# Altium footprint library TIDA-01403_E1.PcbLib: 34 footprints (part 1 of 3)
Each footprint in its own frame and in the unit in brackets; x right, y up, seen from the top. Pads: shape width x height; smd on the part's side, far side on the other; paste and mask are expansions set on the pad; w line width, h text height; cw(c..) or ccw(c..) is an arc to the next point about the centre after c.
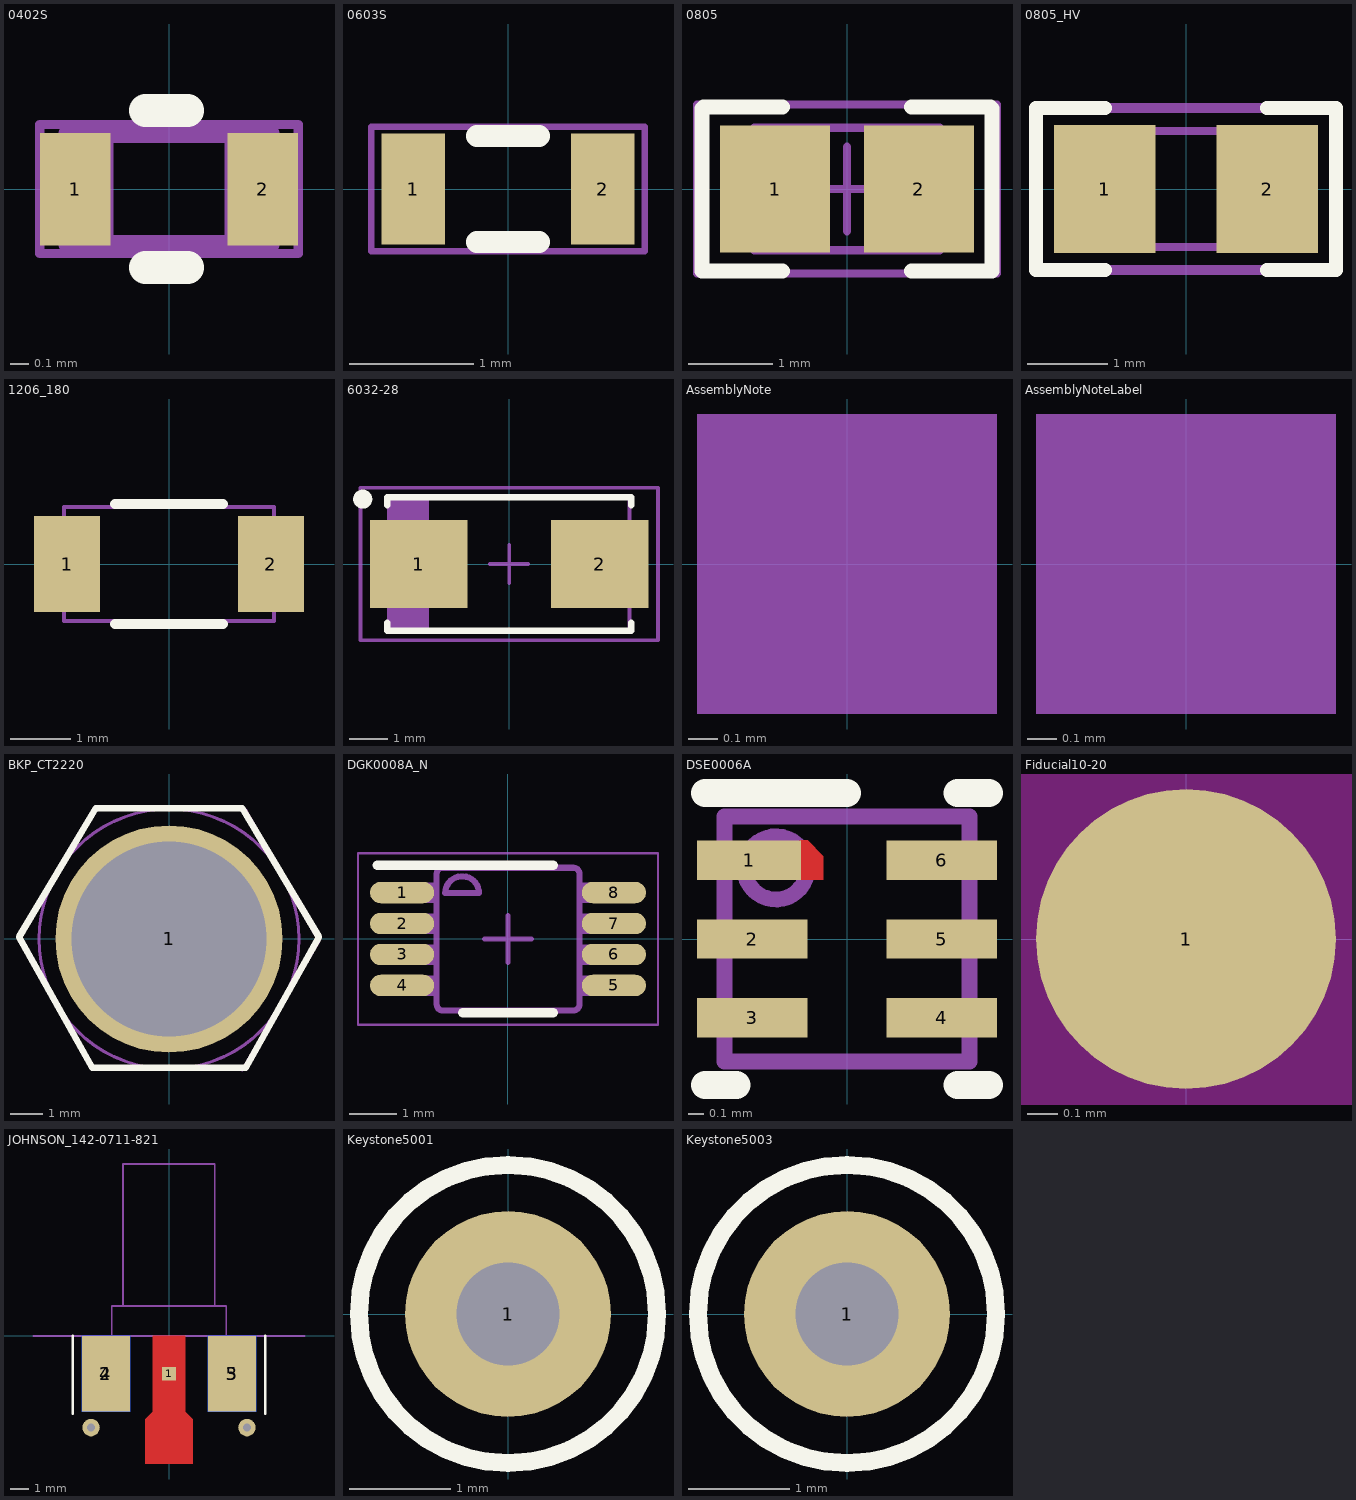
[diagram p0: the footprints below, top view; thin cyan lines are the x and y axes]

## 0402S [mil] "Based on C0402S footprint from PADS legacy"
height 23.62
pads (2):
  rect 15x24 smd: 1(-20,0) 2(20,0)
Top Overlay:
  lines w7: -5,-16.73 4,-16.73 ; -5,16.73 4,16.73
Mechanical 5:
  lines w1.97: -27.56,-13.78 27.56,-13.78 27.56,13.78 -27.56,13.78 -27.56,-13.78
  text ".Designator" at 27,47 h25
Mechanical 13:
  lines w3.94: -13.78,-11.81 -13.78,11.81 ; 13.78,-11.81 13.78,11.81 ; -21.65,-11.81 -21.65,11.81 21.65,11.81 21.65,-11.81 -21.65,-11.81
3D body: height 23.62, standoff 0, extent -21.63,-11.79 -13.8,11.79
3D body: height 23.62, standoff 0, extent -13.76,-11.79 13.76,11.79
3D body: height 23.62, standoff 0, extent 13.8,-11.79 21.63,11.79

## 0603S [mil]
height 39.37
pads (2):
  rect 20x35 smd: 1(-30,0) 2(30,0)
Top Overlay:
  lines w7: -9.84,-16.73 9.84,-16.73 ; -9.84,16.73 9.84,16.73
Mechanical 5:
  lines w1.97: -43.31,-19.68 -43.31,19.68 43.31,19.68 43.31,-19.68 -43.31,-19.68
  text ".Designator" at 30,-29 h25
3D body: height 39.37, standoff 0, extent 21.67,-18.68 34.43,18.68
3D body: height 39.37, standoff 0, extent -21.63,-18.68 21.63,18.68
3D body: height 39.37, standoff 0, extent -34.43,-18.68 -21.67,18.68

## 0805 [mm] "0805 from SM-752 data"
height 1.45
pads (2):
  rect 1.3x1.5 smd: 1(-0.85,0) 2(0.85,0)
Top Overlay:
  lines w0.178: -0.762,-0.968 -1.717,-0.968 -1.717,0.95 -1.699,0.968 -0.762,0.968 ; 0.762,-0.968 1.717,-0.968 1.717,0.95 1.699,0.968 0.762,0.968
Mechanical 5:
  lines w0.1: -1.775,-1 -1.775,1 1.775,1 1.775,-1 -1.775,-1
  text ".Designator" at 0.813,0.305 h0.64
Mechanical 13:
  lines w0.1: -0.65,-0.725 -0.65,0.725 ; 0.65,-0.725 0.65,0.725 ; -1.1,-0.725 -1.1,0.725 1.1,0.725 1.1,-0.725 -1.1,-0.725
Mechanical 15:
  lines w0.1: -0.5,0 0.5,0 ; 0,-0.5 0,0.5 ; -1.775,-1 -1.775,1 1.775,1 1.775,-1 -1.775,-1
3D body: height 1.45, standoff 0, extent 0.651,-0.724 1.099,0.724
3D body: height 1.45, standoff 0, extent -0.649,-0.724 0.649,0.724
3D body: height 1.45, standoff 0, extent -1.099,-0.724 -0.651,0.724

## 0805_HV [mil] "0805 with 30mil clearance between pads"
height 57.09
pads (2):
  rect 50x63 smd: 1(-40,0) 2(40,0)
Top Overlay:
  lines w7: -40,-40 -74,-40 -74,0 -74,40 -40,40 ; 40,-40 74,-40 74,0 74,40 40,40
Mechanical 5:
  lines w5: -74,-40 -74,40 74,40 74,-40 -74,-40
  text ".Designator" at -35,-15 h25
Mechanical 13:
  lines w3.94: -25.59,-28.54 -25.59,28.54 ; 25.59,-28.54 25.59,28.54 ; -43.31,-28.54 -43.31,28.54 43.31,28.54 43.31,-28.54 -43.31,-28.54
3D body: height 57.09, standoff 0, extent 25.61,-28.52 43.29,28.52
3D body: height 57.09, standoff 0, extent -25.57,-28.52 25.57,28.52
3D body: height 57.09, standoff 0, extent -43.29,-28.52 -25.61,28.52

## 1206_180 [mm] "1206_180"
height 1.8
pads (2):
  rect 1.1x1.6 smd: 1(-1.7,0) 2(1.7,0)
Top Overlay:
  lines w0.17: -0.9,-1 0.9,-1 ; -0.9,1 0.9,1
Mechanical 5:
  lines w0.07: -1.75,-0.95 1.75,-0.95 1.75,0.95 -1.75,0.95 -1.75,-0.95
  text ".Designator" at 0.914,0.356 h0.64
3D body: height 1.8, standoff 0, extent -1.749,-0.949 -1.301,0.949
3D body: height 1.8, standoff 0, extent -1.299,-0.949 1.299,0.949
3D body: height 1.8, standoff 0, extent 1.301,-0.949 1.749,0.949

## 6032-28 [mm] "Medium Density IPC based on Vishay Sprague 293D datasheet."
height 2.8
pads (2):
  rect 2.55x2.3 smd: 1(-2.375,0) 2(2.375,0)
Top Overlay:
  circle w0.25: c-3.839,1.7 r0.125
  lines w0.178: -3.2,-1.539 -3.2,-1.75 3.2,-1.75 3.2,-1.539 ; -3.2,1.539 -3.2,1.75 3.2,1.75 3.2,1.539
Mechanical 5:
  rectangle: -3.15,-1.75 -2.15,1.75
  lines w0.1: -2.15,-1.75 -2.15,1.75 ; -3.15,-1.75 3.15,-1.75 3.15,1.75 -3.15,1.75 -3.15,-1.75
  text ".Designator" at 0.889,0.254 h0.64
Mechanical 15:
  lines w0.1: -0.5,0 0.5,0 ; 0,-0.5 0,0.5 ; -3.9,-2 -3.9,2 3.9,2 3.9,-2 -3.9,-2
3D body: height 2.8, standoff 2.8, extent -3.149,-1.749 -2.151,1.749
3D body: height 2.8, standoff 0, extent -3.15,-1.75 3.15,1.75

## AssemblyNote [mm] "Assembly Note"
Mechanical 5:
  rectangle: -0.508,-0.508 0.508,0.508
  text ".Comment" at 1.143,-0.508 h0.64
  text ".Designator" at -4.191,-0.508 h0.64

## AssemblyNoteLabel [mm] "Assembly Note for PCB Labels"
Mechanical 5:
  rectangle: -0.508,-0.508 0.508,0.508
  text ".Designator" at -4.191,-0.508 h0.64
  text "Install label in silkscreened box after final wash.  Text shall be 8 pt font.  Text shall be per the Label Table in the PDF schematic." at 1.143,-0.508 h0.64

## BKP_CT2220 [mm] "Banana Jack Connector Standard Banana Threaded, External (Nut), TH"
height 4.54
pads (1):
  round 7 hole 6: 1(0,0)
Top Overlay:
  lines w0.2: -4.618,0.061 -2.362,-3.969 2.362,-3.969 4.618,0.061 2.256,4.03 -2.256,4.03 -4.618,0.061
Mechanical 5:
  circle w0.1: c0,0 r4
  circle w0.1: c0,0 r3
  lines w0.1: -4.618,0.061 -2.256,4.03 2.362,3.969 4.618,-0.061 2.256,-4.03 -2.362,-3.969 -4.618,0.061
  text ".Designator" at -1.168,-0.076 h0.64
3D body: height 4, standoff -19, extent -4.619,-4 4.619,4

## DGK0008A_N [mm] "TSOP, 8-Leads, Body 3x3mm, Pitch 0.65mm, IPC Medium Density"
height 1.1
pads (8):
  oval 1.35x0.45 smd: 1(-2.225,0.975) 2(-2.225,0.325) 3(-2.225,-0.325) 4(-2.225,-0.975) 5(2.225,-0.975) 6(2.225,-0.325) 7(2.225,0.325) 8(2.225,0.975)
Top Overlay:
  lines w0.2: -2.75,1.55 0.95,1.55 ; -0.95,-1.55 0.95,-1.55
Mechanical 5:
  lines w0.127: -2.45,-1.131 -2.21,-1.131 -2.091,-1.131 -2.087,-1.131 -1.784,-1.131 -1.498,-1.131 -1.498,-0.826 -1.784,-0.826 -2.087,-0.826 -2.091,-0.826 -2.21,-0.826 -2.45,-0.826 -2.45,-1.131 ; -2.45,-0.48 -2.21,-0.48 -2.091,-0.48 -2.087,-0.48 -1.784,-0.48 -1.498,-0.48 -1.498,-0.175 -1.784,-0.175 -2.087,-0.175 -2.091,-0.175 -2.21,-0.175 -2.45,-0.175 -2.45,-0.48 ; -2.45,0.17 -2.21,0.17 -2.091,0.17 -2.087,0.17 -1.784,0.17 -1.498,0.17 -1.498,0.475 -1.784,0.475 -2.087,0.475 -2.091,0.475 -2.21,0.475 -2.45,0.475 -2.45,0.17 ; -2.45,0.82 -2.21,0.82 -2.091,0.82 -2.087,0.82 -1.784,0.82 -1.498,0.82 -1.498,1.125 -1.784,1.125 -2.087,1.125 -2.091,1.125 -2.21,1.125 -2.45,1.125 -2.45,0.82 ; -1.497,-1.377 ccw(c-1.37,-1.374) -1.373,-1.501 -1.371,-1.501 1.373,-1.501 1.375,-1.501 ccw(c1.373,-1.374) 1.5,-1.377 1.5,-1.374 1.5,1.369 1.5,1.372 ccw(c1.373,1.369) 1.375,1.496 1.373,1.496 -1.371,1.496 -1.373,1.496 ccw(c-1.37,1.369) -1.497,1.372 -1.498,1.369 -1.498,-1.374 -1.497,-1.377 ; -1.32,0.962 cw(c-0.964,0.962) -0.609,0.962 -1.32,0.962 ; 1.5,-1.131 1.5,-0.826 1.786,-0.826 2.089,-0.826 2.093,-0.826 2.213,-0.826 2.452,-0.826 2.452,-1.131 2.213,-1.131 2.093,-1.131 2.089,-1.131 1.786,-1.131 1.5,-1.131 ; 1.5,-0.48 1.5,-0.175 1.786,-0.175 2.089,-0.175 2.093,-0.175 2.213,-0.175 2.452,-0.175 2.452,-0.48 2.213,-0.48 2.093,-0.48 2.089,-0.48 1.786,-0.48 1.5,-0.48 ; 1.5,0.17 1.5,0.475 1.786,0.475 2.089,0.475 2.093,0.475 2.213,0.475 2.452,0.475 2.452,0.17 2.213,0.17 2.093,0.17 2.089,0.17 1.786,0.17 1.5,0.17 ; 1.5,0.82 1.5,1.125 1.786,1.125 2.089,1.125 2.093,1.125 2.213,1.125 2.452,1.125 2.452,0.82 2.213,0.82 2.093,0.82 2.089,0.82 1.786,0.82 1.5,0.82
  text ".Designator" at 0.406,-0.61 h0.64
Mechanical 15:
  lines w0.05: -3.15,-1.8 3.15,-1.8 3.15,1.8 -3.15,1.8 -3.15,-1.8
  lines w0.1: -0.5,0 0.5,0 ; 0,-0.5 0,0.5
3D body: height 0.96, standoff 0, extent -2.451,-1.499 2.451,1.499

## DSE0006A [mm] "TI recommended land pattern"
height 0.8
pads (6):
  rect 0.66x0.25 smd: 1(-0.62,0.5)
  rect 0.7x0.25 smd: 2(-0.6,0) 3(-0.6,-0.5) 4(0.6,-0.5) 5(0.6,0) 6(0.6,0.5)
Top Layer:
  region: -0.3,0.625 -0.25,0.625 -0.15,0.525 -0.15,0.375 -0.3,0.375
Top Overlay:
  lines w0.178: -0.9,-0.925 -0.7,-0.925 ; -0.9,0.925 0,0.925 ; 0.7,-0.925 0.9,-0.925 ; 0.7,0.925 0.9,0.925
Mechanical 5:
  circle w0.1: c-0.45,0.45 r0.2
  lines w0.1: -0.775,-0.775 -0.775,0.775 0.775,0.775 0.775,-0.775 -0.775,-0.775
  text ".Designator" at -0.686,1.041 h0.64
3D body: height 0.8, standoff 0.76, extent -0.556,0.354 -0.344,0.566
3D body: height 0.8, standoff 0, extent -0.774,-0.774 0.774,0.774

## FCC_disclaimer [mm]

## Fiducial10-20 [mm]
pads (1):
  round 1 smd mask+0.5: 1(0,0)
Top Layer keep-out:
  circle w1.178: c0,0 r0.5

## JOHNSON_142-0711-821 [mil]
pads (7):
  rect 30x30 smd: 1(0,-82.5)
  rect 105x165 smd: 2(-137.5,-82.5) 3(137.5,-82.5)
  rect 105x165 smd far side: 4(-137.5,-82.5) 5(137.5,-82.5)
  round 38 hole 18: ""(-170,-200) ""(170,-200)
Top Layer:
  region: -51.5,-279.35 -51.5,-181.5 -35,-165 -35,0 35,0 35,-165 51.5,-181.5 51.5,-279.35
Top Overlay:
  lines w6: -210,-170 -210,0 ; 210,-170 210,0
Mechanical 1:
  lines w3.94: -295.28,0 295.28,0
Mechanical 5:
  lines w3.94: -100.01,64.99 -100.01,374.99 99.99,374.99 99.99,64.99 ; -93.01,-0.01 -93.01,-150.01 -125.01,-150.01 -125.01,-0.01 ; -15.01,-0.01 -15.01,-140.01 ; 14.99,-0.01 14.99,-140.01 ; 92.99,-0.01 92.99,-150.01 124.99,-150.01 124.99,-0.01 ; -125.01,-0.01 124.99,-0.01 ; -125.01,-0.01 -125.01,64.99 124.99,64.99 124.99,-0.01 ; -15.01,-140.01 14.99,-140.01 ; -15.01,-140.01 -5.01,-150.01 4.99,-150.01 14.99,-140.01
  text ".Designator" at -20,-195 h25
3D body: height 140, standoff -110, extent -125,-150.01 124.99,374.99

## Keystone5001 [mil] "For Keystone 500x miniature loop terminals"
height 181.1
pads (1):
  round 80 hole 40: 1(0,0)
Top Overlay:
  circle w7: c0,0 r58
Mechanical 5:
  circle w5: c0,0 r58.31
  text ".Designator" at -41,-10 h25
3D body: height 181.97, standoff -118.11, extent -49,-49 49.04,49.24

## Keystone5003 [mil] "For Keystone 500x miniature loop terminals"
height 181.1
pads (1):
  round 80 hole 40: 1(0,0)
Top Overlay:
  circle w7: c0,0 r58
Mechanical 5:
  circle w5: c0,0 r58.31
  text ".Designator" at -45,-10 h25
3D body: height 181.97, standoff -118.11, extent -49,-49 49.04,49.24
